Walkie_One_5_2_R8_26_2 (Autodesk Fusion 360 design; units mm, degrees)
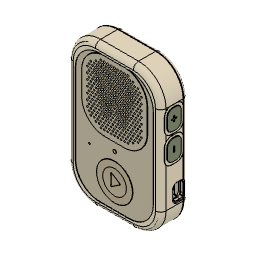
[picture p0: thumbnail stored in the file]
description: Part Number
part number: 2026-09-09-11-52-15-760
part number: 2026-09-09-11-52-15-984
part number: 2026-09-09-11-52-15-986
part number: Open CASCADE STEP translator 7.7 1
part number: 2026-09-09-11-52-16-352
part number: Open CASCADE STEP translator 7.7 2
part number: 2026-09-09-11-52-16-474
part number: Open CASCADE STEP translator 7.7 3
part number: 2026-09-09-11-52-16-584
part number: Open CASCADE STEP translator 7.7 4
